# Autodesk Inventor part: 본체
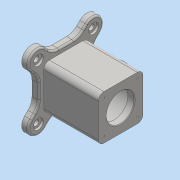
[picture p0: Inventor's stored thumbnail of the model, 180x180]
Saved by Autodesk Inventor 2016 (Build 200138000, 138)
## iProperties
Created: 2019-11
Part Number: 본체
Material: 일반
Document SubType Name: Modeling
Designer: user
Density: 1 g/cm^3
Appearance: 기본값
Author: user
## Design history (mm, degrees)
sketch "스케치1"
  geometry: L1 (-49, -49)-(49, -49); L2 (49, -49)-(49, 49); L3 (49, 49)-(-49, 49); L4 (-49, 49)-(-49, -49); L5 (-49, -49)-(49, 49); L6 (49, -49)-(-49, 49); L7 (49.497, -49.497)-(-49.497, 49.497); L8 (62.225, -36.77)-(-36.77, 62.225); L9 (-62.225, 36.77)-(36.77, -62.225); L10 (49.497, 49.497)-(-49.497, -49.497); L11 (36.77, 62.225)-(-62.225, -36.77); L12 (-36.77, -62.225)-(62.225, 36.77); A1 r 18 centre (49.497, -49.497) between (36.77, -62.225) and (62.225, -36.77); A2 r 18 centre (-49.497, 49.497) between (-36.77, 62.225) and (-62.225, 36.77); A3 r 18 centre (49.497, 49.497) between (62.225, 36.77) and (36.77, 62.225); A4 r 18 centre (-49.497, -49.497) between (-62.225, -36.77) and (-36.77, -62.225); 1 further point
  constraints: 28 end point, 8 point on circle, 8 tangent, 4 centre point, 4 midpoint, 4 parallel, 2 point on line, 1 horizontal, 1 perpendicular
  dimensions: "d72" = 98 distance of L3.end L2.end; "d73" = 98 distance of L2.end L1.end; "d74" = 18 radius of A2; "d75" = 18 radius of A4; "d76" = 140 distance of L10.start L10.end; "d77" = 140 distance of L7.start L7.end
extrude "돌출1" new body sketch "스케치1" distance "d7" = 12; taper "d8" = 0 deg
sketch "스케치2"
  geometry: L1 (-40, -40)-(40, -40); L2 (40, -40)-(40, 40); L3 (40, 40)-(-40, 40); L4 (-40, 40)-(-40, -40); L5 (-40, -40)-(40, 40); L6 (40, -40)-(-40, 40); 1 further point
  constraints: 12 end point, 2 midpoint, 2 parallel, 1 horizontal, 1 perpendicular
  dimensions: "d9" = 80 distance of L3.end L2.end; "d10" = 80 distance of L2.end L1.end
extrude "돌출2" join sketch "스케치2" distance "d11" = 98; taper "d12" = 0 deg
sketch "스케치3"
  geometry: C1 r 9 at (49.497, -49.497); A1 r 18 centre (49.497, -49.497) between (36.77, -62.225) and (62.225, -36.77) reference; 1 further point
  constraints: 1 centre point, 1 concentric
  dimensions: "d13" = 18 diameter of C1
extrude "돌출3" cut sketch "스케치3" distance "d14" = 4; taper "d15" = 0 deg
sketch "스케치4"
  geometry: C1 r 5 at (0, 0); C2 r 9 at (0, 0) reference; 1 further point
  constraints: 1 centre point, 1 concentric
  dimensions: "d16" = 10 diameter of C1
extrude "돌출4" cut sketch "스케치4" distance "d17" = 38.25; taper "d18" = 0 deg
sketch "스케치5"
  geometry: L1 (-12, 63.544)-(-12, 16.456) reference; C1 r 20 at (49, 40); 1 further point
  constraints: 1 centre point, 1 horizontal alignment, 1 midpoint
  dimensions: "d25" = 40 diameter of C1; "d78" = 61 distance from line of L1 C1.centre
extrude "돌출5" join sketch "스케치5" distance "d27" = 15; taper "d28" = 0 deg
sketch "스케치6"
  geometry: C1 r 15 at (0, 0); C2 r 20 at (0, 0) reference; 1 further point
  constraints: 1 centre point, 1 concentric
  dimensions: "d29" = 30 diameter of C1
extrude "돌출6" cut sketch "스케치6" distance "d30" = 8; taper "d31" = 0 deg
sketch "스케치7"
  geometry: C1 r 12.5 at (0, 0); C2 r 15 at (0, 0) reference; 1 further point
  constraints: 1 centre point, 1 concentric
  dimensions: "d32" = 25 diameter of C1
extrude "돌출7" cut sketch "스케치7" distance "d33" = 27.5; taper "d34" = 0 deg
sketch "스케치8"
  geometry: C1 r 25 at (0, 0); 1 further point
  constraints: 1 centre point, 1 coincident
  dimensions: "d35" = 50 diameter of C1
extrude "돌출8" cut sketch "스케치8" distance "d36" = 12; taper "d37" = 0 deg
sketch "스케치9"
  geometry: C1 r 35 at (0, 0); 1 further point
  constraints: 1 centre point, 1 coincident
  dimensions: "d38" = 70 diameter of C1
extrude "돌출9" cut sketch "스케치9" distance "d39" = 86; taper "d40" = 0 deg
sketch "스케치10"
  geometry: C1 r 25 at (0, 0) reference; C2 r 25 at (0, 0); 1 further point
  constraints: 1 centre point, 1 coincident
  dimensions: "d41" = 50 diameter of C2
extrude "돌출10" cut sketch "스케치10" distance "d42" = 12; taper "d43" = 0 deg
sketch "스케치11"
  geometry: L1 (30, 30)-(-30, 30); L2 (-30, 30)-(-30, -30); L3 (-30, -30)-(30, -30); L4 (30, -30)-(30, 30); L5 (30, 30)-(-30, -30); L6 (-30, 30)-(30, -30); 2 further points
  constraints: 12 end point, 2 midpoint, 2 parallel, 1 coincident, 1 horizontal, 1 perpendicular
  dimensions: "d44" = 60 distance of L3.end L2.end; "d45" = 60 distance of L2.end L1.end
hole "구멍1" sketch "스케치11" at (30, -30) diameter "d46" = 3.242; stored, may be unused: countersink angle "d50" = 90 deg, drill point angle "d52" = 118 deg; dims "d47" = 8, "d48" = 4, "d49" = 2, "d51" = 10
node "작업 평면1"
fillet "모깎기1" dims "d59" = 25
fillet "모깎기2" dims "d60" = 3
fillet "모깎기3" dims "d61" = 3
fillet "모깎기4" dims "d62" = 10
chamfer "모따기1" distance "d63" = 1; stored, may be unused: second distance "d64" = 2, angle "d65" = 45 deg
sketch "스케치12"
  geometry: L1 (98, 60)-(98, 0) reference; 2 further points
  constraints: 1 horizontal alignment, 1 midpoint, 1 other
  dimensions: "d66" = 10 distance from line of L1 point (88, 30)
feature "엠보싱1" sketch "스케치12" dims "d67" = 0.5, "d68" = 0
chamfer "모따기2" distance "d69" = 1; stored, may be unused: second distance "d70" = 2, angle "d71" = 45 deg
node "솔리드1"
pattern_linear "직사각형 패턴2" dims "d55" = 60
mirror "대칭1"
pattern_circular "원형 패턴1" dims angle "d80" = 360 deg
